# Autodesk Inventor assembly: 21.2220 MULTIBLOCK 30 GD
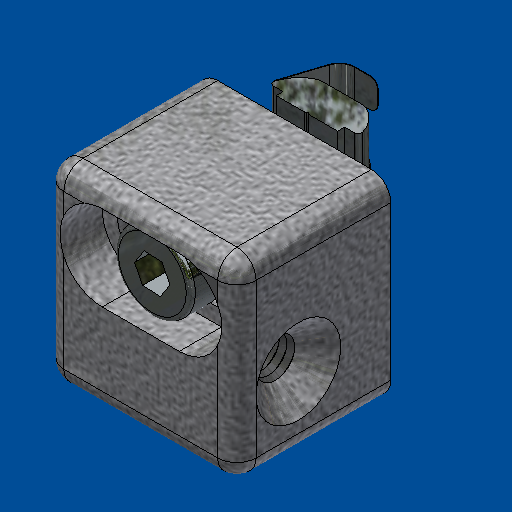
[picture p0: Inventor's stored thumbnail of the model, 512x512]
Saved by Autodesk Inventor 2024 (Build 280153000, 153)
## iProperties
Created: 2025-01
Part Number: 21.2220 MULTIBLOCK 30 GD
Document SubType Name: Assembly
Designer: amoles
Author: amoles
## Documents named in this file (4)
- L:\INVENTOR LIBRARIES\PARTS LIBRARY\30 SERIES\21.2220 MULTIBLOCK 30 GD.iam
- L:\INVENTOR LIBRARIES\PARTS LIBRARY\30 SERIES\SUBCOMPONENTS\21.2220 MULTIBLOCK 30 GD.ipt
- L:\INVENTOR LIBRARIES\PARTS LIBRARY\FASTENING ELEMENTS\SCREWS CAP\21.1265 M6X22.ipt
- L:\INVENTOR LIBRARIES\PARTS LIBRARY\30 SERIES\21.2342_2 M6 SQUARE NUT 30 POS FXG.ipt
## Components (3 placed, 3 different names)
1. 21.2220 MULTIBLOCK 30 GD:1 — Mate:2, Mate:3, Flush:1, Mate:4, Mate:5, Mate:6, Mate:8, Angle:1
2. 21.1265 M6X22 SHCS:1 — Mate:4, Mate:5, Mate:6, Mate:7
3. 21.2342_2 M6 SQUARE NUT 30 POS FXG:1 — Mate:7, Mate:8, Angle:1
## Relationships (9: Mate 7, Flush 1, Angle 1)
- Mate:2: 21.2220 MULTIBLOCK 30 GD:1
- Mate:3: 21.2220 MULTIBLOCK 30 GD:1
- Flush:1: 21.2220 MULTIBLOCK 30 GD:1
- Mate:4: 21.2220 MULTIBLOCK 30 GD:1 ↔ 21.1265 M6X22 SHCS:1
- Mate:5: 21.2220 MULTIBLOCK 30 GD:1 ↔ 21.1265 M6X22 SHCS:1
- Mate:6: 21.2220 MULTIBLOCK 30 GD:1 ↔ 21.1265 M6X22 SHCS:1
- Mate:7: 21.1265 M6X22 SHCS:1 ↔ 21.2342_2 M6 SQUARE NUT 30 POS FXG:1
- Mate:8: 21.2220 MULTIBLOCK 30 GD:1 ↔ 21.2342_2 M6 SQUARE NUT 30 POS FXG:1
- Angle:1: 21.2220 MULTIBLOCK 30 GD:1 ↔ 21.2342_2 M6 SQUARE NUT 30 POS FXG:1
